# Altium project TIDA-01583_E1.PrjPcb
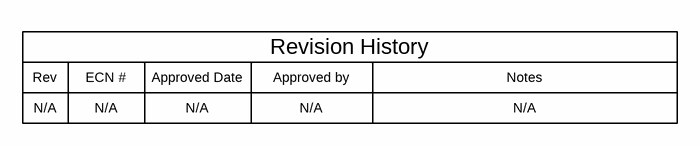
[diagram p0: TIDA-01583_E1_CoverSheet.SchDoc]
TID: TIDA-01583; TechSupport: http://www.ti.com/support; SCH_Rev: E1; PRJ_Title: Ultra-Low Noise Bias Voltage Reference Design for Microbolometer Detectors in Thermal Cameras; PRJ_Number: TIDA-01583; PRJ_Engineer: Sharad Yadav; PRJ_Customer: Public Release; PCB_Rev: E1; PCB_Layout: Sharad Yadav; CopyrightYear: 2018
4 sheets, 128 parts. Net scope: flat (ports and power ports of the same name join across sheets).
Board file: TIDA-01583_E1_PCB.PcbDoc
Sheets:
  TIDA-01583_E1_CoverSheet.SchDoc
  TIDA-01582_E1_Sheet-1.SchDoc
  TIDA-01583_E1_Sheet-2.SchDoc
  TIDA-01583_E1_TID_Hardware.SchDoc

## Sheet TIDA-01583_E1_CoverSheet.SchDoc: System Block Diagram
size 431 x 279 mm; Date: Not shown in title block; ApprovedBy: Not shown in title block; CheckedBy: Not shown in title block; Author: Not shown in title block; CompanyName: Not shown in title block; DrawnBy: Sharad Yadav; Engineer: Not shown in title block; Organization: Not shown in title block; Address1: Not shown in title block; Address2: Not shown in title block; Address3: Not shown in title block; Address4: Not shown in title block; DocumentNumber: 1; Revision: Use project parameter SCH_Rev; SheetNumber: 1; SheetTotal: 4; PageSetup: Record=PageOptions¦CenterHorizontal=True¦CenterVertical=True¦PrintScale=1.00¦XCorrection=1.00¦YCorrection=1.00¦PrintKind=0¦BorderSize=5000000¦LeftOffset=0¦BottomOffset=0¦Orientation=2¦PaperLength=1000¦PaperWidth=1000¦Scale=100¦PaperSource=15¦PrintQuality=600¦MediaType=1¦DitherType=10¦PaperKind=Letter¦PrintScaleMode=1

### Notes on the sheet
- Rev
- N/A
- ECN #
- Approved Date
- Approved by
- Revision History
- Notes

## Sheet TIDA-01582_E1_Sheet-1.SchDoc: LDOs, Connectors, DAC Circuit
size 431 x 279 mm; Date: Not shown in title block; ApprovedBy: Not shown in title block; CheckedBy: Not shown in title block; Author: Not shown in title block; CompanyName: Not shown in title block; DrawnBy: Sharad Yadav; Engineer: Not shown in title block; Organization: Not shown in title block; Address1: Not shown in title block; Address2: Not shown in title block; Address3: Not shown in title block; Address4: Not shown in title block; DocumentNumber: 1; Revision: Use project parameter SCH_Rev; SheetNumber: 2; SheetTotal: 4; PageSetup: Record=PageOptions¦CenterHorizontal=True¦CenterVertical=True¦PrintScale=1.00¦XCorrection=1.00¦YCorrection=1.00¦PrintKind=0¦BorderSize=5000000¦LeftOffset=0¦BottomOffset=0¦Orientation=2¦PaperLength=1000¦PaperWidth=1000¦Scale=100¦PaperSource=15¦PrintQuality=600¦MediaType=1¦DitherType=10¦PaperKind=Letter¦PrintScaleMode=1
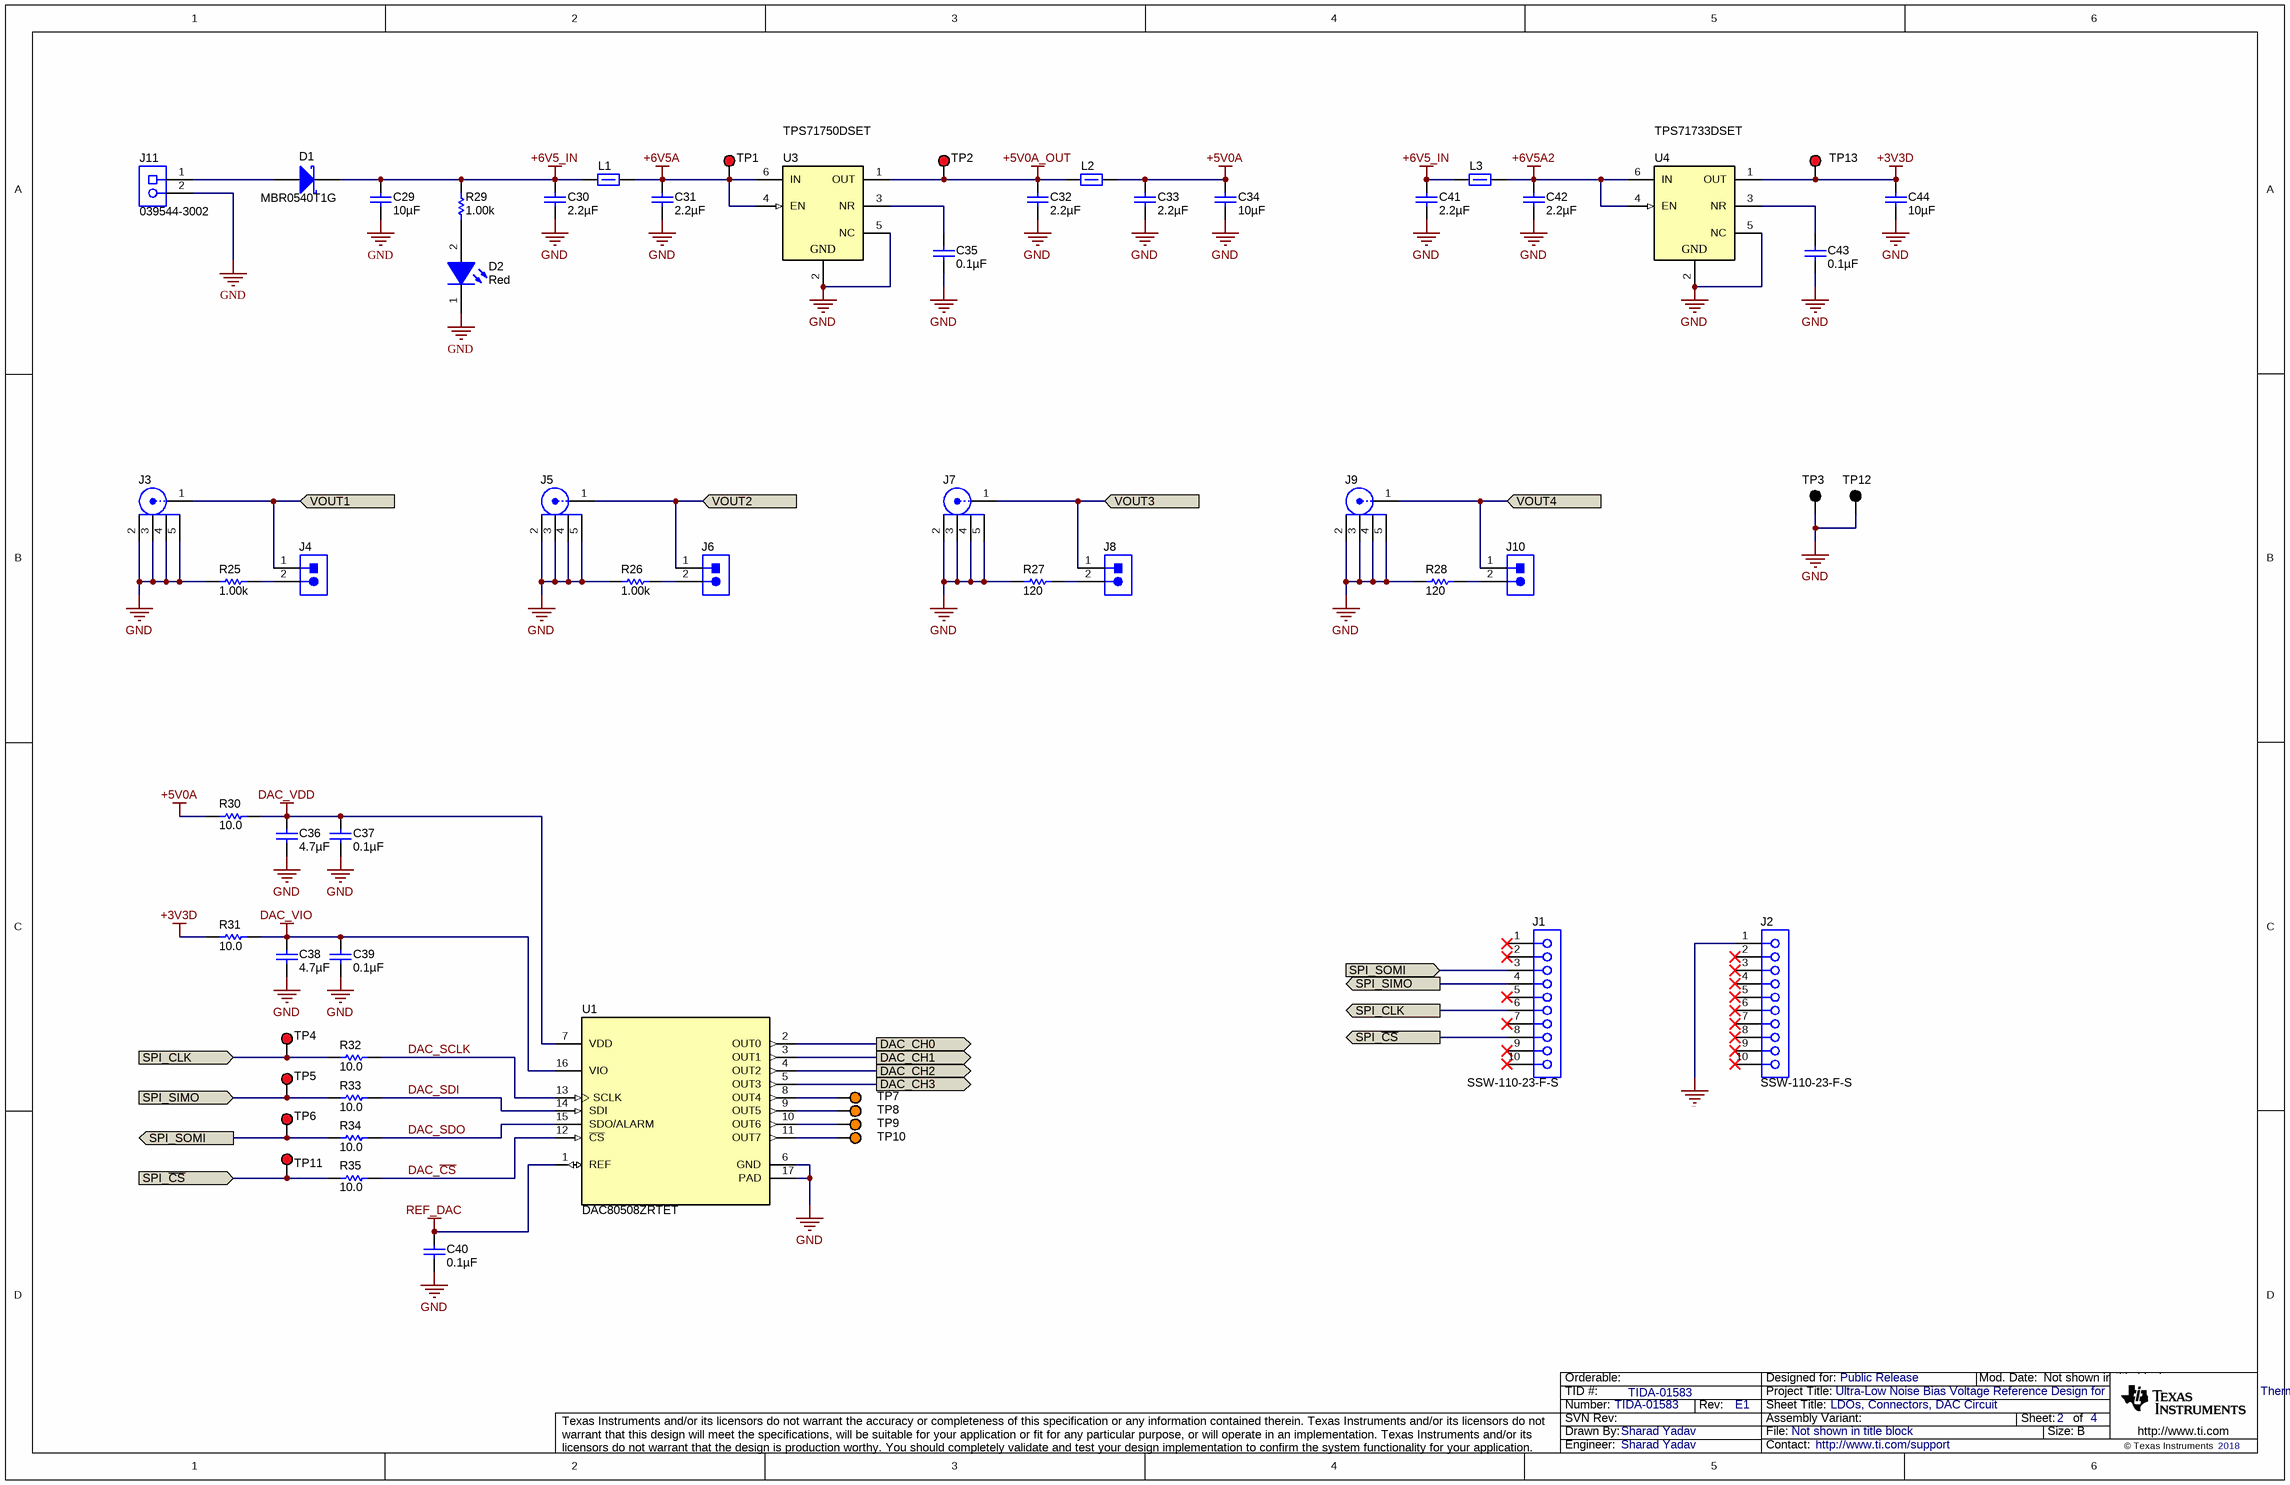
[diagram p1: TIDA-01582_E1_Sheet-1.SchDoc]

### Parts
C29  ValueDisplayed: 10µF  [0603S]  (hidden comment: GRM188R61E106MA73D)
C30  ValueDisplayed: 2.2µF  [0603S]  (hidden comment: EMK107BB7225KA-T)
C31  ValueDisplayed: 2.2µF  [0603S]  (hidden comment: EMK107BB7225KA-T)
C32  ValueDisplayed: 2.2µF  [0603S]  (hidden comment: EMK107BB7225KA-T)
C33  ValueDisplayed: 2.2µF  [0603S]  (hidden comment: EMK107BB7225KA-T)
C34  ValueDisplayed: 10µF  [0603S]  (hidden comment: GRM188R61E106MA73D)
C35  ValueDisplayed: 0.1µF  [0603S]  (hidden comment: C0603C104J3RACTU)
C36  ValueDisplayed: 4.7µF  [0603S]  (hidden comment: GRM188R61E475KE11D)
C37  ValueDisplayed: 0.1µF  [0603S]  (hidden comment: C0603C104J3RACTU)
C38  ValueDisplayed: 4.7µF  [0603S]  (hidden comment: GRM188R61E475KE11D)
C39  ValueDisplayed: 0.1µF  [0603S]  (hidden comment: C0603C104J3RACTU)
C40  ValueDisplayed: 0.1µF  [0603S]  (hidden comment: C0603C104J3RACTU)
C41  ValueDisplayed: 2.2µF  [0603S]  (hidden comment: EMK107BB7225KA-T)
C42  ValueDisplayed: 2.2µF  [0603S]  (hidden comment: EMK107BB7225KA-T)
C43  ValueDisplayed: 0.1µF  [0603S]  (hidden comment: C0603C104J3RACTU)
C44  ValueDisplayed: 10µF  [0603S]  (hidden comment: GRM188R61E106MA73D)
D1  MBR0540T1G  [SOD-123]
D2  value Red  [WL-SMCW_RED]  (hidden comment: 150060RS75000)
J1  SSW-110-23-F-S  [CONN_SSW-110-23-F-S]
J2  SSW-110-23-F-S  [CONN_SSW-110-23-F-S]
J3  142-0711-821  [Johnson_142-0711-821]  (value not drawn)
J4  800-10-002-10-001000  [Mill-Max_800-10-002-10-001000]  (value not drawn)
J5  142-0711-821  [Johnson_142-0711-821]  (value not drawn)
J6  800-10-002-10-001000  [Mill-Max_800-10-002-10-001000]  (value not drawn)
J7  142-0711-821  [Johnson_142-0711-821]  (value not drawn)
J8  800-10-002-10-001000  [Mill-Max_800-10-002-10-001000]  (value not drawn)
J9  142-0711-821  [Johnson_142-0711-821]  (value not drawn)
J10  800-10-002-10-001000  [Mill-Max_800-10-002-10-001000]  (value not drawn)
J11  039544-3002  [Molex_039544-3002]
L1  MMZ1608R150ATA00  [0603S]  (value not drawn)
L2  MMZ1608R150ATA00  [0603S]  (value not drawn)
L3  MMZ1608R150ATA00  [0603S]  (value not drawn)
R25  ValueDisplayed: 1.00k  [0402]  (hidden comment: CRCW04021K00FKED)
R26  ValueDisplayed: 1.00k  [0402]  (hidden comment: CRCW04021K00FKED)
R27  ValueDisplayed: 120  [0402]  (hidden comment: CRCW0402120RJNED)
R28  ValueDisplayed: 120  [0402]  (hidden comment: CRCW0402120RJNED)
R29  ValueDisplayed: 1.00k  [0402]  (hidden comment: CRCW04021K00FKED)
R30  ValueDisplayed: 10.0  [0402]  (hidden comment: CRCW040210R0FKED)
R31  ValueDisplayed: 10.0  [0402]  (hidden comment: CRCW040210R0FKED)
R32  ValueDisplayed: 10.0  [0402]  (hidden comment: CRCW040210R0FKED)
R33  ValueDisplayed: 10.0  [0402]  (hidden comment: CRCW040210R0FKED)
R34  ValueDisplayed: 10.0  [0402]  (hidden comment: CRCW040210R0FKED)
R35  ValueDisplayed: 10.0  [0402]  (hidden comment: CRCW040210R0FKED)
TP1  5000  [Keystone5000]  (value not drawn)
TP2  5000  [Keystone5000]  (value not drawn)
TP3  5001  [Keystone5001]  (value not drawn)
TP4  5000  [Keystone5000]  (value not drawn)
TP5  5000  [Keystone5000]  (value not drawn)
TP6  5000  [Keystone5000]  (value not drawn)
TP7  5003  [Keystone5003]  (value not drawn)
TP8  5003  [Keystone5003]  (value not drawn)
TP9  5003  [Keystone5003]  (value not drawn)
TP10  5003  [Keystone5003]  (value not drawn)
TP11  5000  [Keystone5000]  (value not drawn)
TP12  5001  [Keystone5001]  (value not drawn)
TP13  5000  [Keystone5000]  (value not drawn)
U1  DAC80508ZRTET  [RTE0016D]
U3  TPS71750DSET  [DSE0006A]
U4  TPS71733DSET  [DSE0006A]

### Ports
DAC_CH0 (out), DAC_CH1 (out), DAC_CH2 (out), DAC_CH3 (out), SPI_CLK (in), SPI_CLK (out), SPI_SIMO (in), SPI_SIMO (out), SPI_SOMI (in), SPI_SOMI (out), SPI_~{CS} (in), SPI_~{CS} (out), VOUT1 (in), VOUT2 (in), VOUT3 (in), VOUT4 (in)

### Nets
+3V3D: C44.1 R31.1 TP13.1 U4.1(OUT)
+5V0A: C33.1 C34.1 L2.2 R30.1
+5V0A_OUT: C32.1 L2.1 TP2.1 U3.1(OUT)
+6V5_IN: C29.1 C30.1 C41.1 D1.1(K) L1.1 L3.1 R29.1
+6V5A: C31.1 L1.2 TP1.1 U3.4(EN) U3.6(IN)
+6V5A2: C42.1 L3.2 U4.4(EN) U4.6(IN)
DAC_VDD: C36.1 C37.1 R30.2 U1.7(VDD)
DAC_VIO: C38.1 C39.1 R31.2 U1.16(VIO)
GND: C29.2 C30.2 C31.2 C32.2 C33.2 C34.2 C35.2 C36.2 C37.2 C38.2 C39.2 C40.2 C41.2 C42.2 C43.2 C44.2 D2.1(K) J2.1 J3.2 J3.3 J3.4 J3.5 J5.2 J5.3 J5.4 J5.5 J7.2 J7.3 J7.4 J7.5 J9.2 J9.3 J9.4 J9.5 J11.2 R25.1 R26.1 R27.1 R28.1 TP3.1 TP12.1 U1.6(GND) U1.17(PAD) U3.2(GND) U3.5(NC) U4.2(GND) U4.5(NC)
REF_DAC: C40.1 U1.1(REF)
DAC_~{CS}: R35.2 U1.12(~{CS})
DAC_CH0: U1.2(OUT0) ; port DAC_CH0
DAC_CH1: U1.3(OUT1) ; port DAC_CH1
DAC_CH2: U1.4(OUT2) ; port DAC_CH2
DAC_CH3: U1.5(OUT3) ; port DAC_CH3
DAC_SCLK: R32.2 U1.13(SCLK)
DAC_SDI: R33.2 U1.14(SDI)
DAC_SDO: R34.2 U1.15(SDO/ALARM)
SPI_~{CS}: J1.8 R35.1 TP11.1 ; port SPI_~{CS}
SPI_CLK: J1.6 R32.1 TP4.1 ; port SPI_CLK
SPI_SIMO: J1.4 R33.1 TP5.1 ; port SPI_SIMO
SPI_SOMI: J1.3 R34.1 TP6.1 ; port SPI_SOMI
VOUT1: J3.1 J4.1 ; port VOUT1
VOUT2: J5.1 J6.1 ; port VOUT2
VOUT3: J7.1 J8.1 ; port VOUT3
VOUT4: J9.1 J10.1 ; port VOUT4
NetC35_1: C35.1 U3.3(NR)
NetC43_1: C43.1 U4.3(NR)
NetD1_2: D1.2(A) J11.1
NetD2_2: D2.2(A) R29.2
NetJ4_2: J4.2 R25.2
NetJ6_2: J6.2 R26.2
NetJ8_2: J8.2 R27.2
NetJ10_2: J10.2 R28.2
NetTP7_1: TP7.1 U1.8(OUT4)
NetTP8_1: TP8.1 U1.9(OUT5)
NetTP9_1: TP9.1 U1.10(OUT6)
NetTP10_1: TP10.1 U1.11(OUT7)

Not connected (* = marked no-connect by the designer): J1 1* 2* 5* 7* 9* 10*; J2 2* 3* 4* 5* 6* 7* 8* 9* 10*

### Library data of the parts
C29 C34 C44 = GRM188R61E106MA73D: CAP, CERM, 10 µF, 25 V, +/- 20%, X5R, 0603; Manufacturer: MuRata; Polarized: N; CompType: Capacitor; Value: 10uF; U/M: EA; Cap_F: 0.00001; Tolerance_%: 20; Value1: Unknown; VDC_V: 25; Value2: 25V; TaMin_C: -55; TaMax_C: 85; Cap_Case: 0603; SizeArea_mm2: 1.28; SizeAreaWB_mm2: 4.68; SizeX_mm: 1.6; SizeY_mm: 0.8; SizeZ_mm: 1; AEC Category: Q200
C30-C33 C41 C42 = EMK107BB7225KA-T: CAP, CERM, 2.2 µF, 16 V, +/- 10%, X7R, 0603; Manufacturer: Taiyo Yuden; Polarized: N; CompType: Capacitor; Value: 2.2uF; U/M: EA; Cap_F: 0.0000022; Tolerance_%: 10; Value1: Unknown; VDC_V: 16; Value2: 16V; TaMin_C: -55; TaMax_C: 125; Cap_Case: 0603; SizeArea_mm2: 1.28; SizeAreaWB_mm2: 4.68; SizeX_mm: 1.6; SizeY_mm: 0.8; SizeZ_mm: 1; AEC Category: Q200
C35 C37 C39 C40 C43 = C0603C104J3RACTU: CAP, CERM, 0.1 µF, 25 V, +/- 5%, X7R, 0603; Manufacturer: Kemet; Polarized: N; CompType: Capacitor; Value: 0.1uF; U/M: EA; Cap_F: 0.0000001; Tolerance_%: 5; Value1: Unknown; VDC_V: 25; Value2: 25V; TaMin_C: -55; TaMax_C: 125; Cap_Case: 0603; SizeArea_mm2: 1.28; SizeAreaWB_mm2: 4.68; SizeX_mm: 1.6; SizeY_mm: 0.8; SizeZ_mm: 1; AEC Category: Q200
C36 C38 = GRM188R61E475KE11D: CAP, CERM, 4.7 µF, 25 V, +/- 10%, X5R, 0603; Manufacturer: MuRata; Polarized: N; CompType: Capacitor; Value: 4.7uF; U/M: EA; Cap_F: 0.0000047; Tolerance_%: 10; Value1: Unknown; VDC_V: 25; Value2: 25V; TaMin_C: -55; TaMax_C: 85; Cap_Case: 0603; SizeArea_mm2: 1.28; SizeAreaWB_mm2: 4.68; SizeX_mm: 1.6; SizeY_mm: 0.8; SizeZ_mm: 1; AEC Category: Q200
D1 = MBR0540T1G: Diode, Schottky, 40V, 0.5A, SOD-123; Manufacturer: ON Semiconductor; U/M: EA; Vf_V: 0.51; Value2: 0.51V; Io_A: 0.5; Vr_V: 40; TJmax_C: 150; RJC_CperW: 118
D2 = 150060RS75000: LED, Red, SMD; Manufacturer: Wurth Elektronik; Type: AlInGaP; Vf_V: 2; Value2: 2V; Io_A: 0.03; Vr_V: 5; Tjmax_C: 85; Power_TotalModule: 0.072; Value1: 0.072W; Angle: 140; U/M: EA
J1 J2 = SSW-110-23-F-S: Connector, Receptacle, 100mil, 10x1, Gold plated, TH; Manufacturer: Samtec, Inc.; SymbolCreator: a0411947; U/M: EA
J3 J5 J7 J9 = 142-0711-821: SMA JACK 50 OHM EDGE MNT, SMT; Manufacturer: Cinch Connectivity; SymbolCreator: X0208326; Gender: Female; ContactFinish: Gold; Green_Lifecycle: Not Set; Green_REACh: Incomplete
J4 J6 J8 J10 = 800-10-002-10-001000: Header, 100mil, 2x1, TH; Manufacturer: Mill-Max; SymbolCreator: a0412235
J11 = 039544-3002: Terminal Block, 5.08mm, 2x1, TH; Manufacturer: Molex; SymbolCreator: a0412235; Pitch_mm: 5.08; Gender: Female; Row_Count: 1; ContactFinish: Tin; Current_A: 15; Voltage_V: 300; Cert_UL: Y
L1-L3 = MMZ1608R150ATA00: Ferrite Bead, 15 ohm @ 100 MHz, 1.5 A, 0603; Manufacturer: TDK; ValueDisplayed: 15 ohm; Value: 15 ohm; Imax_A: 1.5; DCR_ohm: 0.05; Value1: 0.05 ohm; Value2: 1.5A; SizeAreaWB_mm2: 4.68; SizeArea_mm2: 1.28; SizeX_mm: 1.6; SizeY_mm: 0.8; SizeZ_mm: 1; ZTyp@100MHz_Ohm: 15
R25 R26 R29 = CRCW04021K00FKED: RES, 1.00 k, 1%, 0.063 W, 0402; Manufacturer: Vishay-Dale; CompType: Resistor; Value: 1.00k; Res_ohm: 1000; Value_Code: 1k00; Tolerance_%: 1; Power_W: 0.063; Value2: 0.063W; VDC_V: 50; TempCo: 100 ppm/C; SizeArea_mm2: 0.5; SizeZ_mm: 0.6; EIA_Code: E96; U/M: EA; AEC Category: Q200
R27 R28 = CRCW0402120RJNED: RES, 120, 5%, 0.063 W, 0402; Manufacturer: Vishay-Dale; CompType: Resistor; Value: 120; Value_Code: 120R; Tolerance_%: 5; Power_W: 0.063; Value2: 0.063W; VDC_V: 50; TempCo: 200 ppm/C; SizeArea_mm2: 0.5; SizeX_mm: 1; SizeZ_mm: 0.6; EIA_Code: E24; U/M: EA; AEC Category: Q200
R30-R35 = CRCW040210R0FKED: RES, 10.0, 1%, 0.063 W, 0402; Manufacturer: Vishay-Dale; CompType: Resistor; Value: 10.0; Res_ohm: 10; Value_Code: 10R0; Tolerance_%: 1; Power_W: 0.063; Value2: 0.063W; VDC_V: 50; TempCo: 100 ppm/C; SizeArea_mm2: 0.5; SizeZ_mm: 0.6; EIA_Code: E96; U/M: EA; AEC Category: Q200
TP1 TP2 TP4-TP6 TP11 TP13 = 5000: Test Point, Miniature, Red, TH; Manufacturer: Keystone; CompType: Test Point Loop; ContactFinish: Silver; Green_Lifecycle: Active; Green_REACh: Passed
TP3 TP12 = 5001: Test Point, Miniature, Black, TH; Manufacturer: Keystone; CompType: Test Point Loop; ContactFinish: Silver; Green_Lifecycle: Active; Green_REACh: Passed
TP7-TP10 = 5003: Test Point, Miniature, Orange, TH; Manufacturer: Keystone; CompType: Test Point Loop; ContactFinish: Silver
U1 = CMP-0080028-1: Octal, 16--Bit, SPI, Voltage Output DAC with Internal Reference, RTE0016D (WQFN-16); Alternate PartNumber: DAC80508ZRTER; Alternate Manufacturer: Texas Instruments; SizeAreaWB_mm2: 16; SizeZ_mm: 0.8; SizeX_mm: 3; SizeArea_mm2: 9; CompType: IC; AEC Category: Q200
U3 = TPS71750DSET: Single Output High PSRR LDO, 150 mA, Fixed 5 V Output, 2.5 to 6.5 V Input, with Low IQ, 6-pin WSON (DSE), -40 to 125 degC, Green (RoHS & no Sb/Br); Manufacturer: Texas Instruments; Alternate PartNumber: Equivalent; Accuracy(%): 3; Fixed Output Options(V): 5; Iout(Max)(A): 0.15; Iq(Typ)(mA): 0.05; SubFamily: Single Channel LDO; Vdo(Typ)(mV): 170; Vin(Max)(V): 6.5; Vin(Min)(V): 2.5
U4 = TPS71733DSET: Single Output High PSRR LDO, 150 mA, Fixed 3.3 V Output, 2.5 to 6.5 V Input, with Low IQ, 6-pin WSON (DSE), -40 to 125 degC, Green (RoHS & no Sb/Br); Manufacturer: Texas Instruments; Alternate PartNumber: Equivalent; Accuracy(%): 3; Fixed Output Options(V): 3.3; Iout(Max)(A): 0.15; Iq(Typ)(mA): 0.05; SubFamily: Single Channel LDO; Vdo(Typ)(mV): 170; Vin(Max)(V): 6.5; Vin(Min)(V): 2.5

## Sheet TIDA-01583_E1_Sheet-2.SchDoc: OPA2192 Amplifiers Circuit
size 431 x 279 mm; Date: Not shown in title block; ApprovedBy: Not shown in title block; CheckedBy: Not shown in title block; Author: Not shown in title block; CompanyName: Not shown in title block; DrawnBy: Sharad Yadav; Engineer: Not shown in title block; Organization: Not shown in title block; Address1: Not shown in title block; Address2: Not shown in title block; Address3: Not shown in title block; Address4: Not shown in title block; DocumentNumber: 1; Revision: Use project parameter SCH_Rev; SheetNumber: 3; SheetTotal: 4; PageSetup: Record=PageOptions¦CenterHorizontal=True¦CenterVertical=True¦PrintScale=1.00¦XCorrection=1.00¦YCorrection=1.00¦PrintKind=0¦BorderSize=5000000¦LeftOffset=0¦BottomOffset=0¦Orientation=2¦PaperLength=1000¦PaperWidth=1000¦Scale=100¦PaperSource=15¦PrintQuality=600¦MediaType=1¦DitherType=10¦PaperKind=Letter¦PrintScaleMode=1
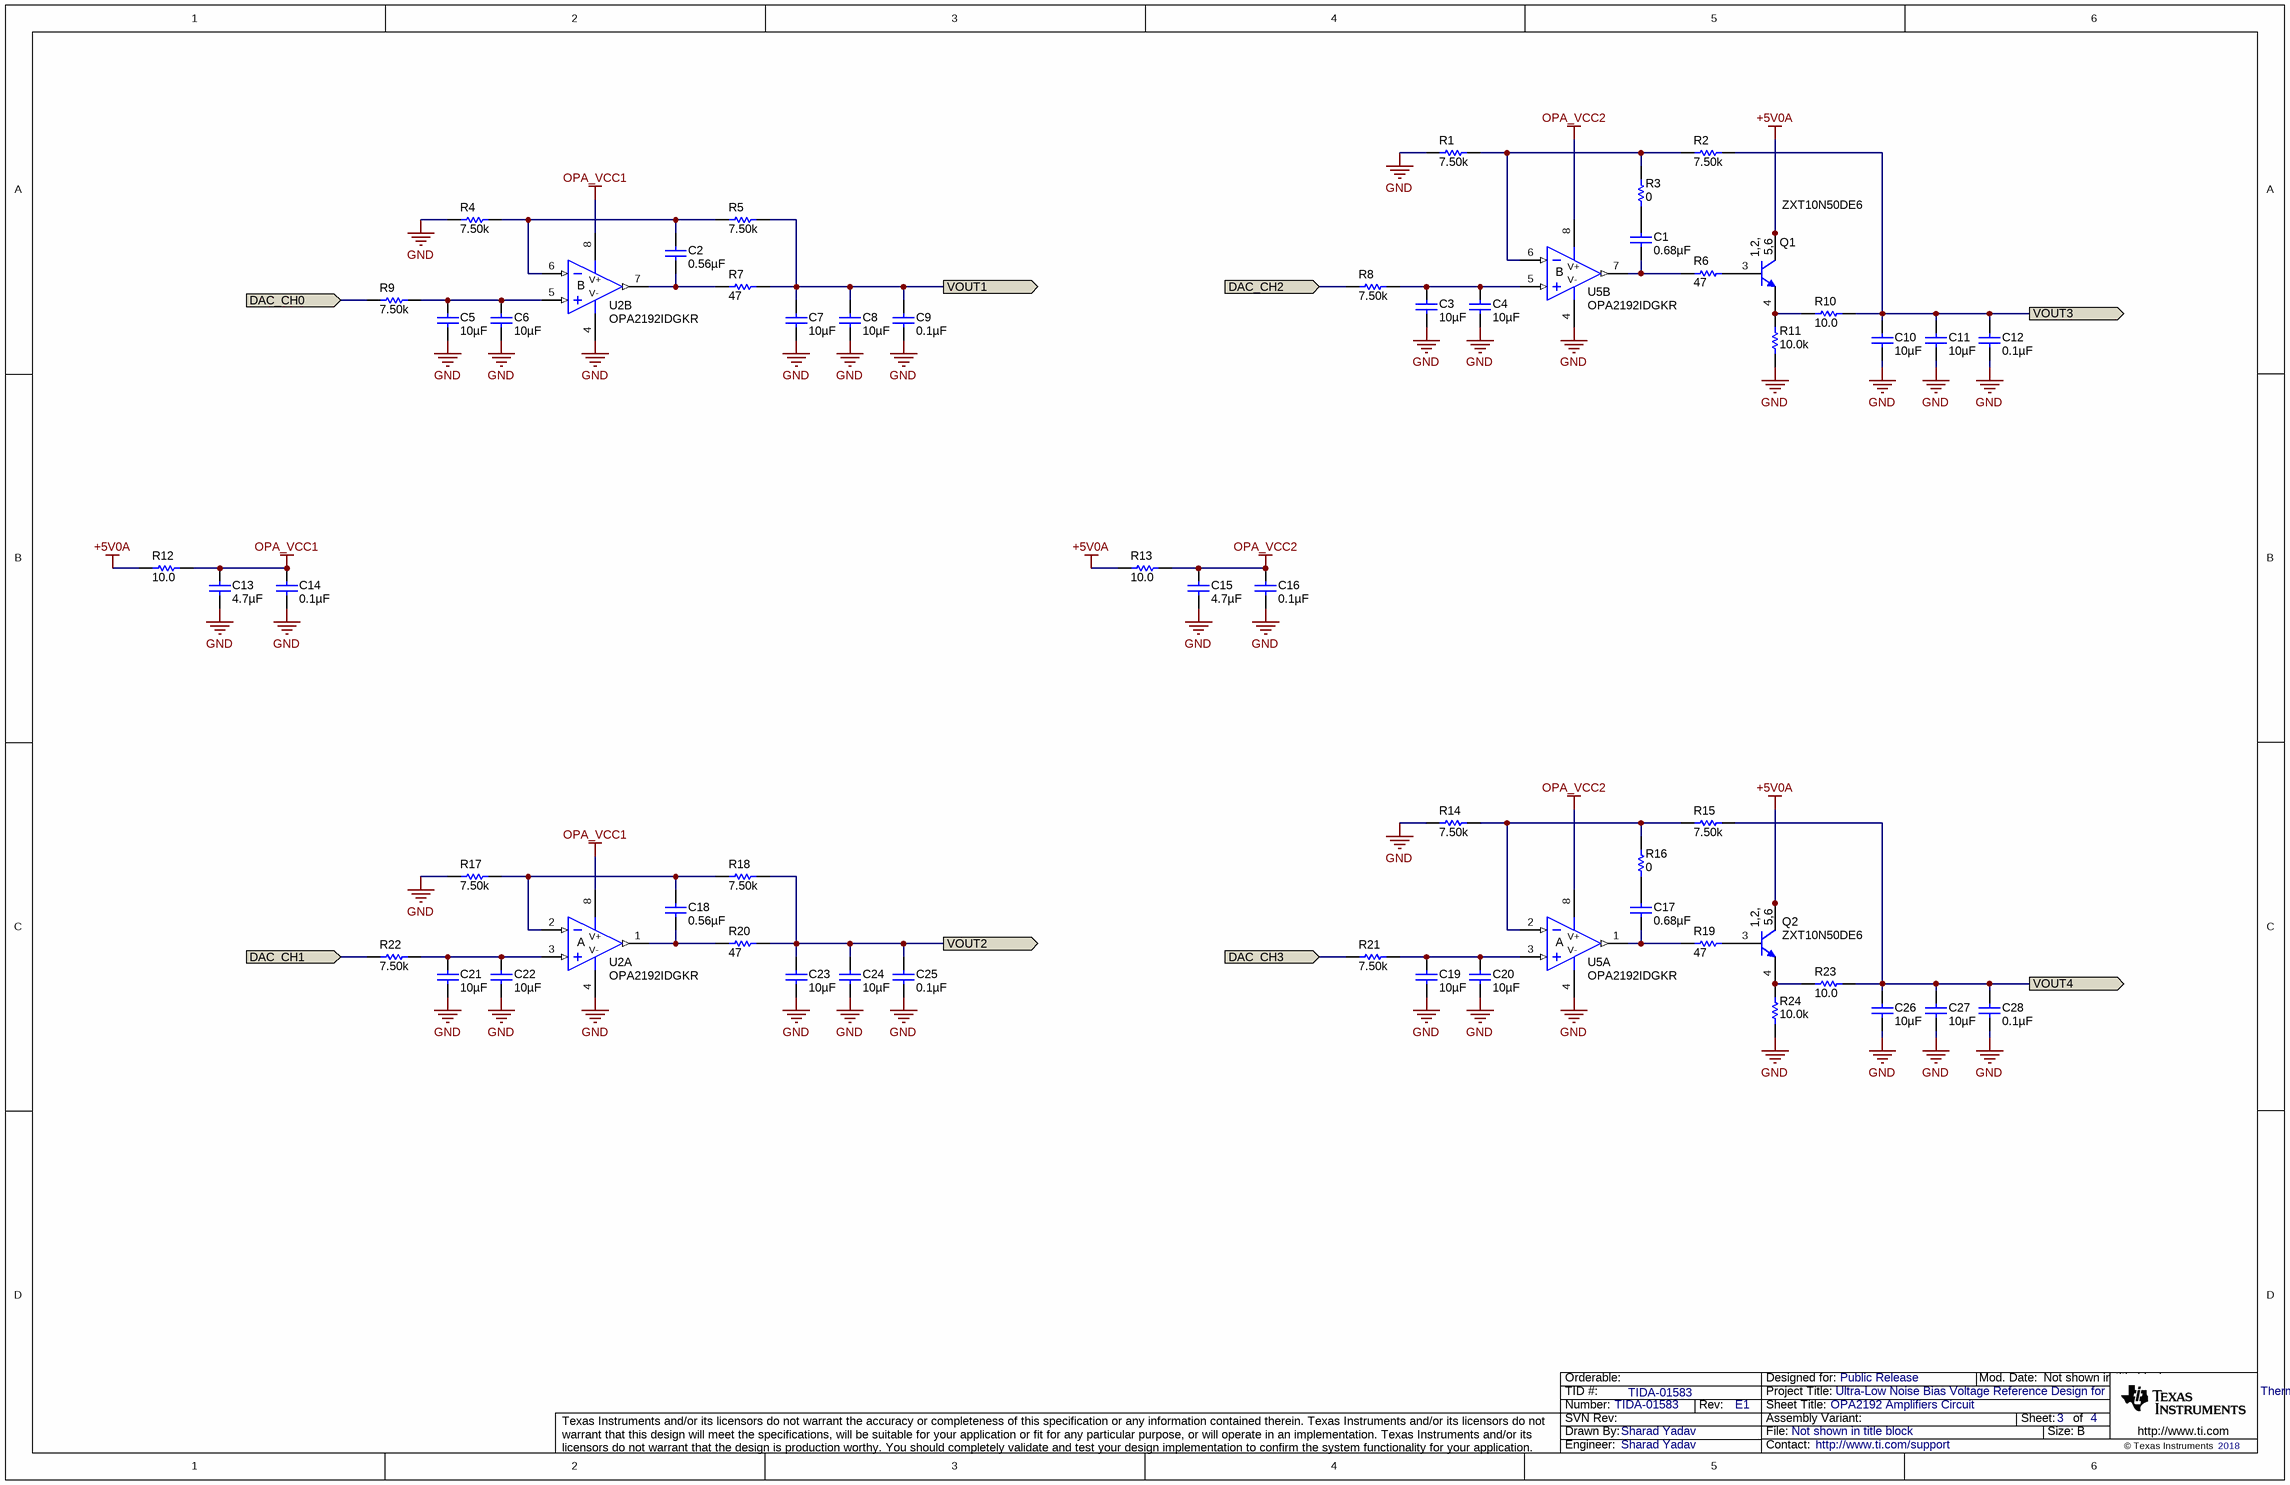
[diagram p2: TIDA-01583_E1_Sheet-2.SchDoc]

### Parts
C1  ValueDisplayed: 0.68µF  [0603S]  (hidden comment: GRM188R71A684KA61D)
C2  ValueDisplayed: 0.56µF  [0603S]  (hidden comment: GRM188R71A564KA61D)
C3  ValueDisplayed: 10µF  [0603S]  (hidden comment: C1608X5R1E106M080AC)
C4  ValueDisplayed: 10µF  [0603S]  (hidden comment: C1608X5R1E106M080AC)
C5  ValueDisplayed: 10µF  [0603S]  (hidden comment: C1608X5R1E106M080AC)
C6  ValueDisplayed: 10µF  [0603S]  (hidden comment: C1608X5R1E106M080AC)
C7  ValueDisplayed: 10µF  [0603S]  (hidden comment: C1608X5R1E106M080AC)
C8  ValueDisplayed: 10µF  [0603S]  (hidden comment: C1608X5R1E106M080AC)
C9  ValueDisplayed: 0.1µF  [0603S]  (hidden comment: C0603C104J3RACTU)
C10  ValueDisplayed: 10µF  [0603S]  (hidden comment: C1608X5R1E106M080AC)
C11  ValueDisplayed: 10µF  [0603S]  (hidden comment: C1608X5R1E106M080AC)
C12  ValueDisplayed: 0.1µF  [0603S]  (hidden comment: C0603C104J3RACTU)
C13  ValueDisplayed: 4.7µF  [0603S]  (hidden comment: GRM188R61E475KE11D)
C14  ValueDisplayed: 0.1µF  [0603S]  (hidden comment: C0603C104J3RACTU)
C15  ValueDisplayed: 4.7µF  [0603S]  (hidden comment: GRM188R61E475KE11D)
C16  ValueDisplayed: 0.1µF  [0603S]  (hidden comment: C0603C104J3RACTU)
C17  ValueDisplayed: 0.68µF  [0603S]  (hidden comment: GRM188R71A684KA61D)
C18  ValueDisplayed: 0.56µF  [0603S]  (hidden comment: GRM188R71A564KA61D)
C19  ValueDisplayed: 10µF  [0603S]  (hidden comment: C1608X5R1E106M080AC)
C20  ValueDisplayed: 10µF  [0603S]  (hidden comment: C1608X5R1E106M080AC)
C21  ValueDisplayed: 10µF  [0603S]  (hidden comment: C1608X5R1E106M080AC)
C22  ValueDisplayed: 10µF  [0603S]  (hidden comment: C1608X5R1E106M080AC)
C23  ValueDisplayed: 10µF  [0603S]  (hidden comment: C1608X5R1E106M080AC)
C24  ValueDisplayed: 10µF  [0603S]  (hidden comment: C1608X5R1E106M080AC)
C25  ValueDisplayed: 0.1µF  [0603S]  (hidden comment: C0603C104J3RACTU)
C26  ValueDisplayed: 10µF  [0603S]  (hidden comment: C1608X5R1E106M080AC)
C27  ValueDisplayed: 10µF  [0603S]  (hidden comment: C1608X5R1E106M080AC)
C28  ValueDisplayed: 0.1µF  [0603S]  (hidden comment: C0603C104J3RACTU)
Q1  ZXT10N50DE6  [SOT-23-6]
Q2  ZXT10N50DE6  [SOT-23-6]
R1  ValueDisplayed: 7.50k  [0402]  (hidden comment: CRCW04027K50FKED)
R2  ValueDisplayed: 7.50k  [0402]  (hidden comment: CRCW04027K50FKED)
R3  ValueDisplayed: 0  [0402]  (hidden comment: ERJ-2GE0R00X)
R4  ValueDisplayed: 7.50k  [0402]  (hidden comment: CRCW04027K50FKED)
R5  ValueDisplayed: 7.50k  [0402]  (hidden comment: CRCW04027K50FKED)
R6  ValueDisplayed: 47  [0402]  (hidden comment: ERJ-2GEJ470X)
R7  ValueDisplayed: 47  [0402]  (hidden comment: ERJ-2GEJ470X)
R8  ValueDisplayed: 7.50k  [0402]  (hidden comment: CRCW04027K50FKED)
R9  ValueDisplayed: 7.50k  [0402]  (hidden comment: CRCW04027K50FKED)
R10  ValueDisplayed: 10.0  [0402]  (hidden comment: CRCW040210R0FKED)
R11  ValueDisplayed: 10.0k  [0402]  (hidden comment: MCR01MRTF1002)
R12  ValueDisplayed: 10.0  [0402]  (hidden comment: CRCW040210R0FKED)
R13  ValueDisplayed: 10.0  [0402]  (hidden comment: CRCW040210R0FKED)
R14  ValueDisplayed: 7.50k  [0402]  (hidden comment: CRCW04027K50FKED)
R15  ValueDisplayed: 7.50k  [0402]  (hidden comment: CRCW04027K50FKED)
R16  ValueDisplayed: 0  [0402]  (hidden comment: ERJ-2GE0R00X)
R17  ValueDisplayed: 7.50k  [0402]  (hidden comment: CRCW04027K50FKED)
R18  ValueDisplayed: 7.50k  [0402]  (hidden comment: CRCW04027K50FKED)
R19  ValueDisplayed: 47  [0402]  (hidden comment: ERJ-2GEJ470X)
R20  ValueDisplayed: 47  [0402]  (hidden comment: ERJ-2GEJ470X)
R21  ValueDisplayed: 7.50k  [0402]  (hidden comment: CRCW04027K50FKED)
R22  ValueDisplayed: 7.50k  [0402]  (hidden comment: CRCW04027K50FKED)
R23  ValueDisplayed: 10.0  [0402]  (hidden comment: CRCW040210R0FKED)
R24  ValueDisplayed: 10.0k  [0402]  (hidden comment: MCR01MRTF1002)
U2  OPA2192IDGKR  [DGK0008A_N]  (parts A,B of 2)
U5  OPA2192IDGKR  [DGK0008A_N]  (parts A,B of 2)

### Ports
DAC_CH0 (in), DAC_CH1 (in), DAC_CH2 (in), DAC_CH3 (in), VOUT1 (out), VOUT2 (out), VOUT3 (out), VOUT4 (out)

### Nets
+5V0A: Q1.1(C) Q1.2(C) Q1.5(C) Q1.6(C) Q2.1(C) Q2.2(C) Q2.5(C) Q2.6(C) R12.1 R13.1
GND: C3.2 C4.2 C5.2 C6.2 C7.2 C8.2 C9.2 C10.2 C11.2 C12.2 C13.2 C14.2 C15.2 C16.2 C19.2 C20.2 C21.2 C22.2 C23.2 C24.2 C25.2 C26.2 C27.2 C28.2 R1.1 R4.1 R11.2 R14.1 R17.1 R24.2 U2.4(V-) U5.4(V-)
OPA_VCC1: C13.1 C14.1 R12.2 U2.8(V+)
OPA_VCC2: C15.1 C16.1 R13.2 U5.8(V+)
DAC_CH0: R9.1 ; port DAC_CH0
DAC_CH1: R22.1 ; port DAC_CH1
DAC_CH2: R8.1 ; port DAC_CH2
DAC_CH3: R21.1 ; port DAC_CH3
VOUT1: C7.1 C8.1 C9.1 R5.2 R7.2 ; port VOUT1
VOUT2: C23.1 C24.1 C25.1 R18.2 R20.2 ; port VOUT2
VOUT3: C10.1 C11.1 C12.1 R2.2 R10.2 ; port VOUT3
VOUT4: C26.1 C27.1 C28.1 R15.2 R23.2 ; port VOUT4
NetC1_1: C1.1 R3.1
NetC1_2: C1.2 R6.1 U5.7(OUT)
NetC2_1: C2.1 R4.2 R5.1 U2.6(IN-)
NetC2_2: C2.2 R7.1 U2.7(OUT)
NetC3_1: C3.1 C4.1 R8.2 U5.5(IN+)
NetC5_1: C5.1 C6.1 R9.2 U2.5(IN+)
NetC17_1: C17.1 R16.1
NetC17_2: C17.2 R19.1 U5.1(OUT)
NetC18_1: C18.1 R17.2 R18.1 U2.2(IN-)
NetC18_2: C18.2 R20.1 U2.1(OUT)
NetC19_1: C19.1 C20.1 R21.2 U5.3(IN+)
NetC21_1: C21.1 C22.1 R22.2 U2.3(IN+)
NetQ1_3: Q1.3(B) R6.2
NetQ1_4: Q1.4(E) R10.1 R11.1
NetQ2_3: Q2.3(B) R19.2
NetQ2_4: Q2.4(E) R23.1 R24.1
NetR1_2: R1.2 R2.1 R3.2 U5.6(IN-)
NetR14_2: R14.2 R15.1 R16.2 U5.2(IN-)

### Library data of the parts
C1 C17 = GRM188R71A684KA61D: CAP, CERM, 0.68 µF, 10 V,+/- 10%, X7R, 0603; Manufacturer: MuRata; Polarized: N; CompType: Capacitor; Value: 0.68uF; U/M: EA; Cap_F: 0.00000068; Tolerance_%: 10; Value2: 10V; TaMin_C: -55; TaMax_C: 125; Cap_Case: 0603; SizeArea_mm2: 1.28; SizeAreaWB_mm2: 4.68; SizeX_mm: 1.6; SizeY_mm: 0.8; SizeZ_mm: 1; AEC Category: Q200; Green_Lifecycle: Active; Green_REACh: Passed
C2 C18 = GRM188R71A564KA61D: CAP, CERM, 0.56 µF, 10 V,+/- 10%, X7R, 0603; Manufacturer: MuRata; Polarized: N; CompType: Capacitor; Value: 0.56uF; U/M: EA; Cap_F: 0.00000056; Tolerance_%: 10; Value2: 10V; TaMin_C: -55; TaMax_C: 125; Cap_Case: 0603; SizeArea_mm2: 1.28; SizeAreaWB_mm2: 4.68; SizeX_mm: 1.6; SizeY_mm: 0.8; SizeZ_mm: 1; AEC Category: Q200
C3-C8 C10 C11 C19-C24 C26 C27 = C1608X5R1E106M080AC: CAP, CERM, 10 µF, 25 V, +/- 20%, X5R, 0603; Manufacturer: TDK; Polarized: N; CompType: Capacitor; Value: 10uF; U/M: EA; Cap_F: 0.00001; Tolerance_%: 20; ESR_ohm: 0.004639; Value1: 0.004639 ohm; VDC_V: 25; Value2: 25V; IRMS_A: 2.41407; TaMin_C: -55; TaMax_C: 85; Cap_Case: 0603; SizeArea_mm2: 1.28; SizeAreaWB_mm2: 4.68; SizeX_mm: 1.6; SizeY_mm: 0.8; SizeZ_mm: 1; AEC Category: Q200; Green_Lifecycle: Active; Green_REACh: Passed
C9 C12 C14 C16 C25 C28 = C0603C104J3RACTU: as C35 on sheet TIDA-01582_E1_Sheet-1
C13 C15 = GRM188R61E475KE11D: as C36 on sheet TIDA-01582_E1_Sheet-1
Q1 Q2 = ZXT10N50DE6, Zetex: Transistor, NPN, 50 V, 3 A, SOT-23-6; Manufacturer: Zetex; CompType: BJT; PNP: 0; NPN: 1; Vceo_V: 50; Vcesat1_V: 0.145; Value: 50 V; IcRated_A: 3; Value1: 3 A; HfeMax: 225; TaMin_C: -55; TaMax_C: 150; SizeAreaWB_mm2: 14.82; SizeArea_mm2: 8.12; SizeX_mm: 2.9; SizeY_mm: 2.8; SizeZ_mm: 1.15; U/M: EA; AEC Category: Q101
R1 R2 R4 R5 R8 R9 R14 R15 R17 R18 R21 R22 = CRCW04027K50FKED: RES, 7.50 k, 1%, 0.063 W, 0402; Manufacturer: Vishay-Dale; CompType: Resistor; Value: 7.50k; Res_ohm: 7500; Value_Code: 7k50; Tolerance_%: 1; Power_W: 0.063; Value2: 0.063W; VDC_V: 50; TempCo: 100 ppm/C; SizeArea_mm2: 0.5; SizeZ_mm: 0.6; EIA_Code: E96; U/M: EA; AEC Category: Q200; Green_Lifecycle: Active; Green_REACh: Passed
R3 R16 = ERJ-2GE0R00X: RES, 0, 5%, 0.063 W, 0402; Manufacturer: Panasonic; CompType: Resistor; Value: 0; Value_Code: 0000; Tolerance_%: 5; Power_W: 0.063; Value2: 0.063W; VDC_V: 50; TempCo: 600 ppm/C; SizeArea_mm2: 0.5; SizeX_mm: 1; SizeZ_mm: 0.6; EIA_Code: E24; U/M: EA; AEC Category: Q200; Green_Lifecycle: Active; Green_REACh: Passed
R6 R7 R19 R20 = ERJ-2GEJ470X: RES, 47, 5%, 0.1 W, AEC-Q200 Grade 0, 0402; Manufacturer: Panasonic; CompType: Resistor; Value: 47; Value_Code: 47R0; Tolerance_%: 5; Power_W: 0.1; Value2: 0.1W; TempCo: 200 ppm/C; SizeArea_mm2: 0.5; SizeX_mm: 1; SizeZ_mm: 0.6; EIA_Code: E24; U/M: EA; AEC Category: Q200; AEC Qualified: Y; AEC Grade: 0
R10 R12 R13 R23 = CRCW040210R0FKED: as R30 on sheet TIDA-01582_E1_Sheet-1
R11 R24 = MCR01MRTF1002: RES, 10.0 k, 0.1%, 0.063 W, 0402; Manufacturer: Rohm; CompType: Resistor; Value: 10.0k; Res_ohm: 10000; Value_Code: 10k0; Tolerance_%: 0.1; Power_W: 0.063; Value2: 0.063W; VDC_V: 50; TempCo: 100 ppm/C; SizeArea_mm2: 0.5; SizeX_mm: 1; SizeZ_mm: 0.6; EIA_Code: E192; U/M: EA; AEC Category: Q200; AEC Qualified: N
U2 U5 = OPA2192IDGKR: 36-V, Precision, Rail-to-Rail Input/Output, Low Offset Voltage, Low Input Bias Current Op Amp with e-trim, DGK0008A (VSSOP-8); Manufacturer: Texas Instruments; CompType: IC; SizeArea_mm2: 15.655; SizeAreaWB_mm2: 35.955; SizeX_mm: 5.05; SizeY_mm: 3.1; SizeZ_mm: 1.1; U/M: EA

## Sheet TIDA-01583_E1_TID_Hardware.SchDoc: Hardware
size 431 x 279 mm; Date: Not shown in title block; ApprovedBy: Not shown in title block; CheckedBy: Not shown in title block; Author: Not shown in title block; CompanyName: Not shown in title block; DrawnBy: Sharad Yadav; Engineer: Not shown in title block; Organization: Not shown in title block; Address1: Not shown in title block; Address2: Not shown in title block; Address3: Not shown in title block; Address4: Not shown in title block; DocumentNumber: 1; Revision: Use project parameter SCH_Rev; SheetNumber: 4; SheetTotal: 4; PageSetup: Record=PageOptions¦CenterHorizontal=True¦CenterVertical=True¦PrintScale=1.00¦XCorrection=1.00¦YCorrection=1.00¦PrintKind=0¦BorderSize=5000000¦LeftOffset=0¦BottomOffset=0¦Orientation=2¦PaperLength=1000¦PaperWidth=1000¦Scale=100¦PaperSource=15¦PrintQuality=600¦MediaType=1¦DitherType=10¦PaperKind=Letter¦PrintScaleMode=1
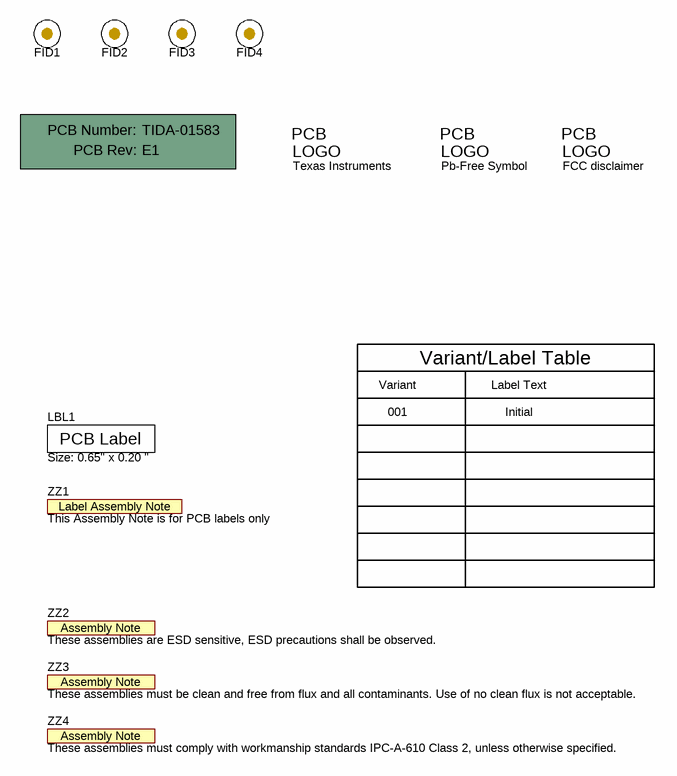
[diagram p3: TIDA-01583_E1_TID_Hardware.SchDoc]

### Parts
!PCB1  Printed Circuit Board  (value not drawn)  (mechanical)
FID1  Fiducial  [Fiducial10-20]  (value not drawn)
FID2  Fiducial  [Fiducial10-20]  (value not drawn)
FID3  Fiducial  [Fiducial10-20]  (value not drawn)
FID4  Fiducial  [Fiducial10-20]  (value not drawn)
LBL1  Size: 0.65" x 0.20 "  [Label_650x200]
Logo1  Texas Instruments  [TI_Stacked_Overlay_Small]  (no BOM)
Logo2  Pb-Free Symbol  [Pb-Free_Overlay_Small]  (no BOM)
Logo3  FCC disclaimer  [FCC_disclaimer]  (no BOM)
ZZ1  This Assembly Note is for PCB labels only  [AssemblyNoteLabel]  (no BOM)
ZZ2  These assemblies are ESD sensitive, ESD precautions shall be observed.  [AssemblyNote]  (no BOM)
ZZ3  These assemblies must be clean and free from flux and all contaminants. Use of no clean flux is not acceptable.  [AssemblyNote]  (no BOM)
ZZ4  These assemblies must comply with workmanship standards IPC-A-610 Class 2, unless otherwise specified.  [AssemblyNote]  (no BOM)

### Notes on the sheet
- Variant
- Variant/Label Table
- Label Text
- 001
- Initial

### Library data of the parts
!PCB1 = PCB: Manufacturer: Any; PartNumber: TIDA-01583; SymbolCreator: a0412235
FID1-FID4 = Fiducial: Fiducial mark.  There is nothing to buy or mount.; SymbolCreator: codlsc
LBL1 = THT-14-423-10: Thermal Transfer Printable Labels, 0.650" W x 0.200" H - 10,000 per roll; Manufacturer: Brady; SymbolCreator: a0412235; CompType: Label
Logo1 = TI_Logo: Texas Instrument Corporate Signature; SymbolCreator: codlsc
Logo2 = Pb-Free: SymbolCreator: a0412235
Logo3 = FCC_disclaimer: SymbolCreator: codlsc
ZZ1 = AssemblyNoteLabel: SymbolCreator: a0412235
ZZ2-ZZ4 = AssemblyNote: SymbolCreator: codlsc

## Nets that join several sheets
+5V0A: TIDA-01582_E1_Sheet-1 (C33.1 C34.1 L2.2 R30.1), TIDA-01583_E1_Sheet-2 (10 pins)
GND: TIDA-01582_E1_Sheet-1 (47 pins), TIDA-01583_E1_Sheet-2 (32 pins)
DAC_CH0: TIDA-01582_E1_Sheet-1 (U1.2), TIDA-01583_E1_Sheet-2 (R9.1)
DAC_CH1: TIDA-01582_E1_Sheet-1 (U1.3), TIDA-01583_E1_Sheet-2 (R22.1)
DAC_CH2: TIDA-01582_E1_Sheet-1 (U1.4), TIDA-01583_E1_Sheet-2 (R8.1)
DAC_CH3: TIDA-01582_E1_Sheet-1 (U1.5), TIDA-01583_E1_Sheet-2 (R21.1)
VOUT1: TIDA-01582_E1_Sheet-1 (J3.1 J4.1), TIDA-01583_E1_Sheet-2 (5 pins)
VOUT2: TIDA-01582_E1_Sheet-1 (J5.1 J6.1), TIDA-01583_E1_Sheet-2 (5 pins)
VOUT3: TIDA-01582_E1_Sheet-1 (J7.1 J8.1), TIDA-01583_E1_Sheet-2 (5 pins)
VOUT4: TIDA-01582_E1_Sheet-1 (J9.1 J10.1), TIDA-01583_E1_Sheet-2 (5 pins)

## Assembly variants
001: not fitted FID1 FID2 FID3
Variant of TIDA-01583_E1: all parts fitted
